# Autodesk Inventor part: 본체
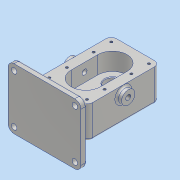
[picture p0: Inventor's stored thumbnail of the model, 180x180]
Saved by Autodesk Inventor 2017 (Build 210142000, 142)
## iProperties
Part Number: 본체
Material: 알루미늄 6061
Document SubType Name: Modeling
Designer: MRC
Density: 2.7 g/cm^3
Appearance: 알루미늄 - 평지
Mass: 1472.54 g
Surface Area: 818.394 cm^2
Volume: 545.387 cm^3
Author: MRC
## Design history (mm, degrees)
sketch "스케치1"
  geometry: L1 (-40, 60)-(40, 60); L2 (40, 60)-(40, -60); L3 (40, -60)-(-40, -60); L4 (-40, -60)-(-40, 60); 3 further points
  constraints: 8 end point, 2 midpoint, 2 parallel, 1 horizontal, 1 horizontal alignment, 1 perpendicular, 1 vertical alignment
  dimensions: "d0" = 80 distance of L1.start L1.end; "d1" = 120 distance of L3.end L1.start
extrude "돌출1" new body sketch "스케치1" distance "d3" = 14; taper "d4" = 0 deg; dims "d6" = 39, "d7" = 0
fillet "모깎기1" dims "d5" = 9
sketch "스케치2"
  geometry: L1 (0, -22)-(0, 22); L2 (24, -22)-(24, 22); L3 (-24, 22)-(-24, -22); A1 r 24 centre (0, -22) between (-24, -22) and (24, -22); A2 r 24 centre (0, 22) between (24, 22) and (-24, 22); 2 further points
  constraints: 8 end point, 4 point on circle, 4 tangent, 2 centre point, 1 coincident, 1 midpoint, 1 parallel, 1 vertical
  dimensions: "d8" = 92 dimension on A1 A2; "d9" = 44 distance of L2.start L2.end
extrude "돌출2" cut sketch "스케치2" distance "d10" = 29; taper "d11" = 0 deg
sketch "스케치3"
  geometry: C1 r 12.5 at (0, 22); C2 r 12.5 at (0, -22); A1 r 24 centre (0, 22) between (24, 22) and (-24, 22) reference; A2 r 24 centre (0, -22) between (-24, -22) and (24, -22) reference; 1 further point
  constraints: 2 centre point, 2 coincident
  dimensions: "d12" = 25 diameter of C1; "d13" = 25 diameter of C2
extrude "돌출3" cut sketch "스케치3" distance "d14" = 15; taper "d15" = 0 deg
sketch "스케치4"
  geometry: L1 (-31, 60)-(31, 60) reference; L2 (40, 51)-(40, -51) reference; L3 (-40, -51)-(-40, 51) reference; L4 (31, -60)-(-31, -60) reference; C1 r 12.5 at (0, 22) reference; C2 r 19 at (0, 22); A1 r 9 centre (-31, 51) between (-31, 60) and (-40, 51) reference; A2 r 9 centre (31, 51) between (40, 51) and (31, 60) reference; A3 r 9 centre (31, -51) between (31, -60) and (40, -51) reference; A4 r 9 centre (-31, -51) between (-40, -51) and (-31, -60) reference; 1 further point
  constraints: 1 centre point, 1 coincident
  dimensions: "d16" = 38 diameter of C2
extrude "돌출4" join sketch "스케치4" distance "d17" = 17; taper "d18" = 0 deg
hole "구멍1" diameter "d21" = 17; stored, may be unused: countersink angle "d25" = 90 deg, drill point angle "d27" = 118 deg; dims "d19" = 10, "d20" = 10, "d22" = 6, "d23" = 28, "d24" = 7.3, "d26" = 8
chamfer "모따기1" distance "d28" = 0.7; stored, may be unused: second distance "d29" = 2, angle "d30" = 30 deg
fillet "모깎기2" dims "d31" = 0.5
sketch "스케치5"
  geometry: C1 r 11 at (-39, 51); 1 further point
  constraints: 1 centre point, 1 coincident
  dimensions: "d32" = 22 diameter of C1
extrude "돌출5" join sketch "스케치5" distance "d33" = 8; taper "d34" = 0 deg
hole "구멍2" diameter "d37" = 8.376; stored, may be unused: countersink angle "d41" = 90 deg, drill point angle "d43" = 118 deg; dims "d35" = 10, "d36" = 10, "d38" = 20, "d39" = 28, "d40" = 7.3, "d42" = 27.3
sketch "스케치6"
  geometry: A1 r 9 centre (-31, -51) between (-40, -51) and (-31, -60) reference; A2 r 9 centre (31, -51) between (31, -60) and (40, -51) reference; A3 r 9 centre (31, 51) between (40, 51) and (31, 60) reference; A4 r 9 centre (-31, 51) between (-31, 60) and (-40, 51) reference; 9 further points
  constraints: 4 coincident, 4 vertical alignment, 2 horizontal alignment
  dimensions: "d44" = 29 distance of point (-31, 22) point (-31, 51); "d45" = 44 distance of point (-31, -22) point (-31, 22)
hole "구멍3" sketch "스케치6" at (-31, 51), (31, 51), (31, -51), (-31, -51), (-31, -22), (-31, 22), (31, 22), (31, -22) diameter "d46" = 4.134; stored, may be unused: countersink angle "d50" = 90 deg, drill point angle "d52" = 118 deg; dims "d47" = 10, "d48" = 28, "d49" = 7.3, "d51" = 12
sketch "스케치8"
  geometry: L1 (-80, 44)-(-90, 44); L2 (-90, 44)-(-90, -56); L3 (-90, -56)-(-80, -56); L4 (-80, -56)-(-80, 44); L5 (46, -15)-(46, 14) reference; L6 (46, 14)-(60, 14) reference; L7 (60, 14)-(60, -39) reference; L8 (60, -39)-(41, -39) reference; L9 (41, -39)-(41, -56) reference; L10 (41, -56)-(36.404, -56) reference; L11 (36.404, -56)-(36, -55.3) reference; L12 (36, -55.3)-(36, -49.2) reference; L13 (35.5, -48.7)-(30.5, -48.7) reference; L14 (30.5, -48.7)-(30.5, -30) reference; L15 (30.5, -30)-(34.5, -30) reference; L16 (34.5, -30)-(34.5, -15) reference; L17 (34.5, -15)-(46, -15) reference; L18 (-60, -39)-(-60, 14) reference; L19 (-60, 14)-(-46, 14) reference; L20 (-46, 14)-(-46, -15) reference; L21 (-46, -15)-(-34.5, -15) reference; L22 (-34.5, -15)-(-34.5, -30) reference; L23 (-34.5, -30)-(-9.5, -30) reference; L24 (-9.5, -30)-(-9.5, -15) reference; L25 (-9.5, -15)-(9.5, -15) reference; L26 (9.5, -15)-(9.5, -30) reference; L27 (9.5, -30)-(13.5, -30) reference; L28 (13.5, -30)-(13.5, -48.7) reference; L29 (13.5, -48.7)-(8.5, -48.7) reference; L30 (8, -49.2)-(8, -55.3) reference; L31 (8, -55.3)-(7.596, -56) reference; L32 (7.596, -56)-(3, -56) reference; L33 (3, -56)-(3, -39) reference; L34 (3, -39)-(-60, -39) reference; A1 r 0.5 centre (35.5, -49.2) between (36, -49.2) and (35.5, -48.7) reference; A2 r 0.5 centre (8.5, -49.2) between (8.5, -48.7) and (8, -49.2) reference; 1 further point
  constraints: 8 end point, 2 parallel, 1 collinear, 1 horizontal, 1 perpendicular
  dimensions: "d55" = 90 distance from line of point (0, 0) L2; "d56" = 10 distance of L1.start L1.end; "d57" = 100 distance of L1.end L2.end
extrude "돌출6" join sketch "스케치8" stored distance "d58" = 120; taper "d59" = 0 deg
fillet "모깎기3" dims "d60" = 10
sketch "스케치10"
  geometry: L1 (-60, 2.453)-(-80, 14); L2 (-80, 14)-(-80, -39); L3 (-80, -39)-(-60, -27.453); L4 (-60, -27.453)-(-60, 2.453); L5 (-80, -56)-(-90, -56) reference; L6 (-80, 34)-(-80, -46) reference; L7 (-60, -39)-(-60, 14) reference; 1 further point
  constraints: 8 end point, 2 collinear, 1 equal length, 1 parallel, 1 vertical
  dimensions: "d62" = 17 distance from line of L2.end L5; "d63" = 53 distance of L1.end L2.end; "d64" = 60 deg angle of L1 L2
extrude "돌출7" join sketch "스케치10" stored distance "d65" = 48; taper "d66" = 0 deg
sketch "스케치11"
  geometry: A1 r 10 centre (0, 90) between (0, 100) and (-10, 90) reference; A2 r 10 centre (0, 10) between (-10, 10) and (0, 0) reference; A3 r 10 centre (100, 10) between (100, 0) and (110, 10) reference; A4 r 10 centre (100, 90) between (110, 90) and (100, 100) reference; 5 further points
  constraints: 4 coincident
hole "구멍4" sketch "스케치11" at (0, 10), (0, 90), (100, 90), (100, 10) diameter "d67" = 9; stored, may be unused: countersink angle "d71" = 90 deg, drill point angle "d73" = 0 deg; dims "d68" = 10, "d69" = 28, "d70" = 7.3, "d72" = 9
sketch "스케치12" dims "d0" = 80, "d1" = 120
  geometry: L1 (-10, 10)-(-10, 90) reference; L2 (100, 0)-(0, 0) reference; 2 further points
  constraints: 1 other
  dimensions: "d74" = 60 distance from line of point (50, 10) L1; "d75" = 10 distance from line of point (50, 10) L2
feature "엠보싱1" sketch "스케치12" dims "d0" = 80, "d1" = 120, "d76" = 0.5, "d77" = 0
chamfer "모따기2" distance "d78" = 1; stored, may be unused: second distance "d79" = 2, angle "d80" = 30 deg
fillet "모깎기4" dims "d81" = 3
fillet "모깎기5" dims "d82" = 3
node "솔리드1"
mirror "미러1"
node "절단 모서리 투영1"
node "절단 모서리 투영2"
